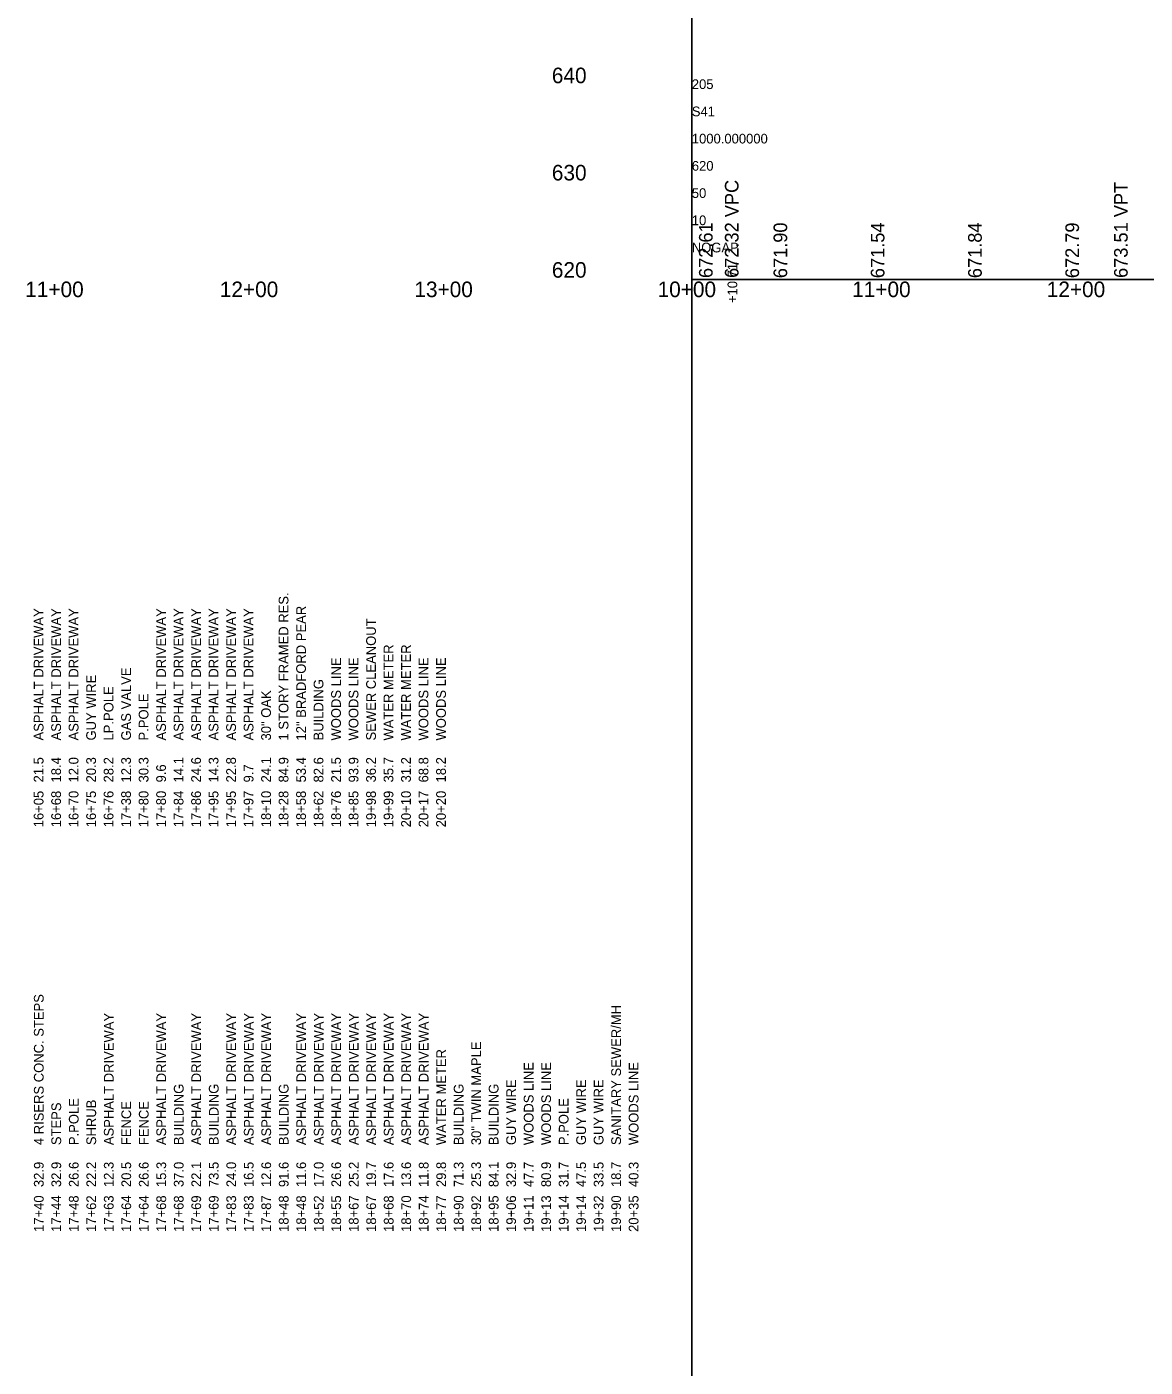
# Model space of a CAD drawing. Extents: x 16382402 to 16388022, y 46194326 to 46202918.
# Drawn here: x 16384835 to 16385409, y 46196212 to 46196901 of the extents above; entities that cross this region are included whole.
import ezdxf

# ---------------------------------------------------------------- set-up
doc = ezdxf.new("R2010")
doc.units = 0
for name, color, linetype in [('RD_DDB_ElevTX', 7, 'Continuous'), ('RD_DDB_Profile_Lbl', 7, 'Continuous'), ('RD_DDB_StaTX', 7, 'Continuous'), ('RD_DDB_StripGrade', 7, 'Continuous'), ('RD_GPK_Profile_Cell', 7, 'Continuous'), ('RD_TX_Bldg', 7, 'Continuous'), ('RD_TX_Misc1', 7, 'Continuous')]:
    doc.layers.add(name, color=color, linetype=linetype)

msp = doc.modelspace()

# ---------------------------------------------------------------- linework, layer by layer
at = {"layer": 'RD_GPK_Profile_Cell'}
for q in [(16385176.35, 46198020.8), (16386476.35, 46196770.8), (16385176.35, 46195520.8)]:
    msp.add_line((16385176.35, 46196770.8), q, dxfattribs=at)

# ---------------------------------------------------------------- texts
at = {"layer": 'RD_DDB_ElevTX'}
for s, p in [('640', (16385104.41, 46196871.8)), ('630', (16385104.41, 46196821.8)), ('620', (16385104.41, 46196771.8))]:
    msp.add_text(s, height=8, dxfattribs=at).set_placement(p)
at = {"layer": 'RD_DDB_Profile_Lbl'}
msp.add_text('672.61', height=7, rotation=90, dxfattribs=at).set_placement((16385187.03, 46196771.62))
at = {"layer": 'RD_DDB_StaTX'}
msp.add_text('+10.71', height=5, rotation=90, dxfattribs=at).set_placement((16385199.7, 46196758.75))
for s, p in [('11+00', (16384833.76, 46196761.8)), ('12+00', (16384933.76, 46196761.8)), ('13+00', (16385033.76, 46196761.8)), ('10+00', (16385158.76, 46196761.8)), ('11+00', (16385258.76, 46196761.8)), ('12+00', (16385358.76, 46196761.8))]:
    msp.add_text(s, height=8, dxfattribs=at).set_placement(p)
at = {"layer": 'RD_DDB_StripGrade'}
for s, p in [('672.32 VPC', (16385200.35, 46196771.66)), ('673.51 VPT', (16385400.35, 46196771.66)), ('671.90', (16385225.35, 46196771.55)), ('671.54', (16385275.35, 46196771.55)), ('671.84', (16385325.35, 46196771.55)), ('672.79', (16385375.35, 46196771.55))]:
    msp.add_text(s, height=7, rotation=90, dxfattribs=at).set_placement(p)
at = {"layer": 'RD_GPK_Profile_Cell'}
for s, p in [('205', (16385176.35, 46196868.8)), ('S41', (16385176.35, 46196854.8)), ('1000.000000', (16385176.35, 46196840.8)), ('620', (16385176.35, 46196826.8)), ('50', (16385176.35, 46196812.8)), ('10', (16385176.35, 46196798.8)), ('NOGAP', (16385176.35, 46196784.8))]:
    msp.add_text(s, height=5, dxfattribs=at).set_placement(p)
at = {"layer": 'RD_TX_Bldg'}
for s, p in [('1 STORY FRAMED RES.', (16384969.02, 46196533.81)), ('ASPHALT DRIVEWAY', (16384843.14, 46196533.81)), ('ASPHALT DRIVEWAY', (16384852.13, 46196533.81)), ('ASPHALT DRIVEWAY', (16384861.12, 46196533.81)), ('ASPHALT DRIVEWAY', (16384906.08, 46196533.81)), ('ASPHALT DRIVEWAY', (16384915.07, 46196533.81)), ('ASPHALT DRIVEWAY', (16384924.06, 46196533.81)), ('ASPHALT DRIVEWAY', (16384933.05, 46196533.81)), ('ASPHALT DRIVEWAY', (16384942.05, 46196533.81)), ('ASPHALT DRIVEWAY', (16384951.04, 46196533.81)), ('12" BRADFORD PEAR', (16384978.01, 46196533.81)), ('SEWER CLEANOUT', (16385013.98, 46196533.81)), ('WATER METER', (16385022.97, 46196533.81)), ('WATER METER', (16385031.96, 46196533.81)), ('WOODS LINE', (16384996, 46196533.81)), ('WOODS LINE', (16385004.99, 46196533.81)), ('WOODS LINE', (16385040.95, 46196533.81)), ('WOODS LINE', (16385049.95, 46196533.81)), ('GAS VALVE', (16384888.09, 46196533.81)), ('GUY WIRE', (16384870.11, 46196533.81)), ('BUILDING', (16384987, 46196533.81)), ('LP.POLE', (16384879.1, 46196533.81)), ('P.POLE', (16384897.09, 46196533.81)), ('30" OAK', (16384960.03, 46196533.81)), ('21.5', (16384843.14, 46196512.24)), ('18.4', (16384852.13, 46196512.24)), ('12.0', (16384861.12, 46196512.24)), ('20.3', (16384870.11, 46196512.24)), ('28.2', (16384879.1, 46196512.24)), ('12.3', (16384888.09, 46196512.24)), ('30.3', (16384897.09, 46196512.24)), ('9.6', (16384906.08, 46196512.24)), ('14.1', (16384915.07, 46196512.24)), ('24.6', (16384924.06, 46196512.24)), ('14.3', (16384933.05, 46196512.24)), ('22.8', (16384942.05, 46196512.24)), ('9.7', (16384951.04, 46196512.24)), ('24.1', (16384960.03, 46196512.24)), ('84.9', (16384969.02, 46196512.24)), ('53.4', (16384978.01, 46196512.24)), ('82.6', (16384987, 46196512.24)), ('21.5', (16384996, 46196512.24)), ('93.9', (16385004.99, 46196512.24)), ('36.2', (16385013.98, 46196512.24)), ('35.7', (16385022.97, 46196512.24)), ('31.2', (16385031.96, 46196512.24)), ('68.8', (16385040.95, 46196512.24)), ('18.2', (16385049.95, 46196512.24)), ('16+05', (16384843.14, 46196489.18)), ('16+68', (16384852.13, 46196489.18)), ('16+70', (16384861.12, 46196489.18)), ('16+75', (16384870.11, 46196489.18)), ('16+76', (16384879.1, 46196489.18)), ('17+38', (16384888.09, 46196489.18)), ('17+80', (16384897.09, 46196489.18)), ('17+80', (16384906.08, 46196489.18)), ('17+84', (16384915.07, 46196489.18)), ('17+86', (16384924.06, 46196489.18)), ('17+95', (16384933.05, 46196489.18)), ('17+95', (16384942.05, 46196489.18)), ('17+97', (16384951.04, 46196489.18)), ('18+10', (16384960.03, 46196489.18)), ('18+28', (16384969.02, 46196489.18)), ('18+58', (16384978.01, 46196489.18)), ('18+62', (16384987, 46196489.18)), ('18+76', (16384996, 46196489.18)), ('18+85', (16385004.99, 46196489.18)), ('19+98', (16385013.98, 46196489.18)), ('19+99', (16385022.97, 46196489.18)), ('20+10', (16385031.96, 46196489.18)), ('20+17', (16385040.95, 46196489.18)), ('20+20', (16385049.95, 46196489.18))]:
    msp.add_text(s, height=5, rotation=90, dxfattribs=at).set_placement(p)
at = {"layer": 'RD_TX_Misc1'}
for s, p in [('4 RISERS CONC. STEPS', (16384843.22, 46196325.74)), ('SANITARY SEWER/MH', (16385139.95, 46196325.74)), ('ASPHALT DRIVEWAY', (16384879.19, 46196325.74)), ('ASPHALT DRIVEWAY', (16384906.16, 46196325.74)), ('ASPHALT DRIVEWAY', (16384924.14, 46196325.74)), ('ASPHALT DRIVEWAY', (16384942.13, 46196325.74)), ('ASPHALT DRIVEWAY', (16384951.12, 46196325.74)), ('ASPHALT DRIVEWAY', (16384960.11, 46196325.74)), ('ASPHALT DRIVEWAY', (16384978.09, 46196325.74)), ('ASPHALT DRIVEWAY', (16384987.09, 46196325.74)), ('ASPHALT DRIVEWAY', (16384996.08, 46196325.74)), ('ASPHALT DRIVEWAY', (16385005.07, 46196325.74)), ('ASPHALT DRIVEWAY', (16385014.06, 46196325.74)), ('ASPHALT DRIVEWAY', (16385023.05, 46196325.74)), ('ASPHALT DRIVEWAY', (16385032.05, 46196325.74)), ('ASPHALT DRIVEWAY', (16385041.04, 46196325.74)), ('30" TWIN MAPLE', (16385068.01, 46196325.74)), ('WATER METER', (16385050.03, 46196325.74)), ('WOODS LINE', (16385094.99, 46196325.74)), ('WOODS LINE', (16385103.98, 46196325.74)), ('WOODS LINE', (16385148.94, 46196325.74)), ('BUILDING', (16384915.15, 46196325.74)), ('BUILDING', (16384933.14, 46196325.74)), ('BUILDING', (16384969.1, 46196325.74)), ('BUILDING', (16385059.02, 46196325.74)), ('BUILDING', (16385077, 46196325.74)), ('GUY WIRE', (16385086, 46196325.74)), ('GUY WIRE', (16385121.96, 46196325.74)), ('GUY WIRE', (16385130.95, 46196325.74)), ('P.POLE', (16384861.2, 46196325.74)), ('SHRUB', (16384870.19, 46196325.74)), ('P.POLE', (16385112.97, 46196325.74)), ('STEPS', (16384852.21, 46196325.74)), ('FENCE', (16384888.18, 46196325.74)), ('FENCE', (16384897.17, 46196325.74)), ('32.9', (16384843.22, 46196304.16)), ('32.9', (16384852.21, 46196304.16)), ('26.6', (16384861.2, 46196304.16)), ('22.2', (16384870.19, 46196304.16)), ('12.3', (16384879.19, 46196304.16)), ('20.5', (16384888.18, 46196304.16)), ('26.6', (16384897.17, 46196304.16)), ('15.3', (16384906.16, 46196304.16)), ('37.0', (16384915.15, 46196304.16)), ('22.1', (16384924.14, 46196304.16)), ('73.5', (16384933.14, 46196304.16)), ('24.0', (16384942.13, 46196304.16)), ('16.5', (16384951.12, 46196304.16)), ('12.6', (16384960.11, 46196304.16)), ('91.6', (16384969.1, 46196304.16)), ('11.6', (16384978.09, 46196304.16)), ('17.0', (16384987.09, 46196304.16)), ('26.6', (16384996.08, 46196304.16)), ('25.2', (16385005.07, 46196304.16)), ('19.7', (16385014.06, 46196304.16)), ('17.6', (16385023.05, 46196304.16)), ('13.6', (16385032.05, 46196304.16)), ('11.8', (16385041.04, 46196304.16)), ('29.8', (16385050.03, 46196304.16)), ('71.3', (16385059.02, 46196304.16)), ('25.3', (16385068.01, 46196304.16)), ('84.1', (16385077, 46196304.16)), ('32.9', (16385086, 46196304.16)), ('47.7', (16385094.99, 46196304.16)), ('80.9', (16385103.98, 46196304.16)), ('31.7', (16385112.97, 46196304.16)), ('47.5', (16385121.96, 46196304.16)), ('33.5', (16385130.95, 46196304.16)), ('18.7', (16385139.95, 46196304.16)), ('40.3', (16385148.94, 46196304.16)), ('17+40', (16384843.22, 46196281.11)), ('17+44', (16384852.21, 46196281.11)), ('17+48', (16384861.2, 46196281.11)), ('17+62', (16384870.19, 46196281.11)), ('17+63', (16384879.19, 46196281.11)), ('17+64', (16384888.18, 46196281.11)), ('17+64', (16384897.17, 46196281.11)), ('17+68', (16384906.16, 46196281.11)), ('17+68', (16384915.15, 46196281.11)), ('17+69', (16384924.14, 46196281.11)), ('17+69', (16384933.14, 46196281.11)), ('17+83', (16384942.13, 46196281.11)), ('17+83', (16384951.12, 46196281.11)), ('17+87', (16384960.11, 46196281.11)), ('18+48', (16384969.1, 46196281.11)), ('18+48', (16384978.09, 46196281.11)), ('18+52', (16384987.09, 46196281.11)), ('18+55', (16384996.08, 46196281.11)), ('18+67', (16385005.07, 46196281.11)), ('18+67', (16385014.06, 46196281.11)), ('18+68', (16385023.05, 46196281.11)), ('18+70', (16385032.05, 46196281.11)), ('18+74', (16385041.04, 46196281.11)), ('18+77', (16385050.03, 46196281.11)), ('18+90', (16385059.02, 46196281.11)), ('18+92', (16385068.01, 46196281.11)), ('18+95', (16385077, 46196281.11)), ('19+06', (16385086, 46196281.11)), ('19+11', (16385094.99, 46196281.11)), ('19+13', (16385103.98, 46196281.11)), ('19+14', (16385112.97, 46196281.11)), ('19+14', (16385121.96, 46196281.11)), ('19+32', (16385130.95, 46196281.11)), ('19+90', (16385139.95, 46196281.11)), ('20+35', (16385148.94, 46196281.11))]:
    msp.add_text(s, height=5, rotation=90, dxfattribs=at).set_placement(p)

doc.saveas('drawing.dxf')
